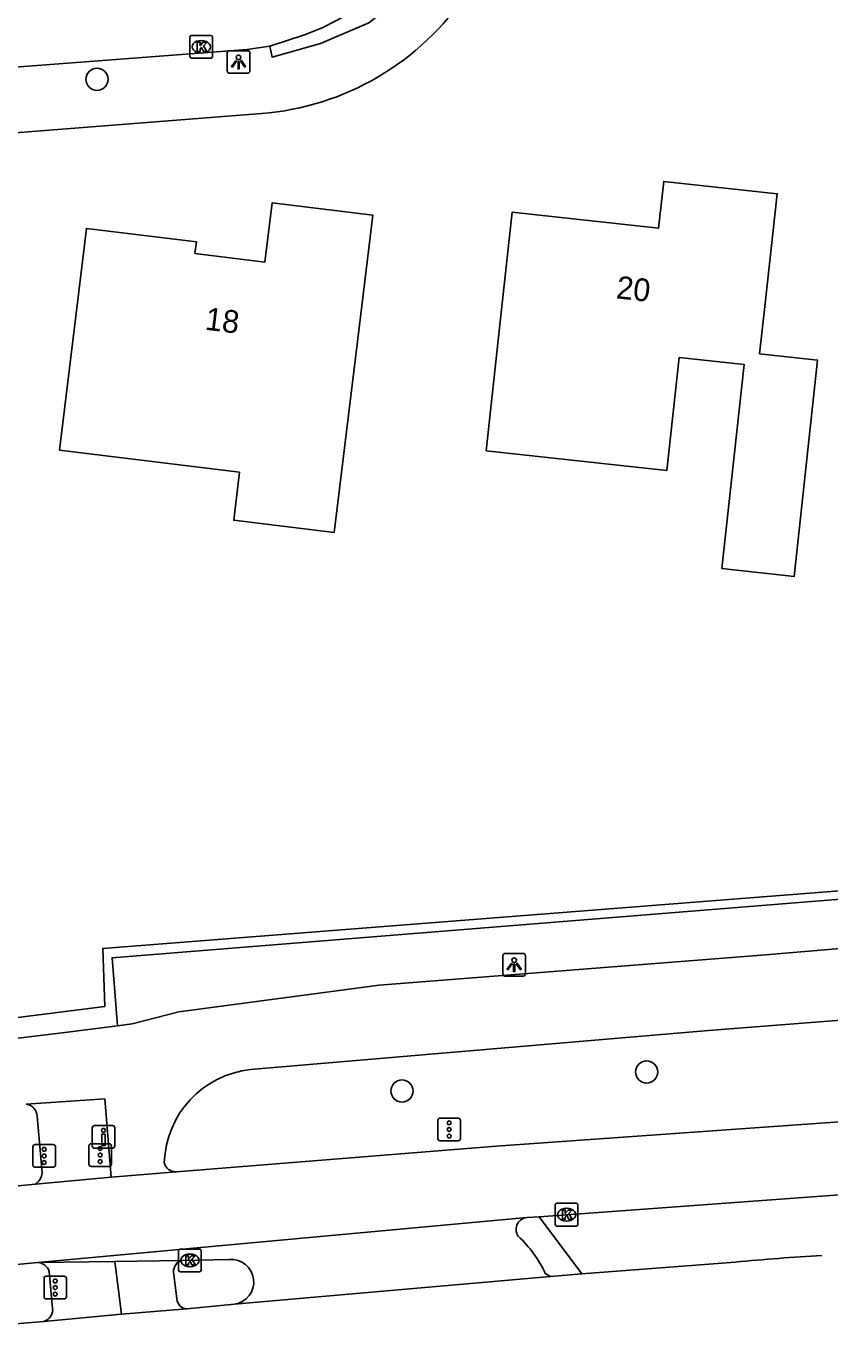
# Model space of a CAD drawing. Extents: x 162398 to 163643, y 386453 to 387397.
# Drawn here: x 163129.2 to 163164.7, y 386513.4 to 386571.3 of the extents above; entities that cross this region are included whole.
import ezdxf

# ---------------------------------------------------------------- set-up
doc = ezdxf.new("R2010")
doc.units = 0
for name, color, linetype in [('IMGEO_Boom', 7, 'Continuous'), ('IMGEO_Drukknoppaal', 7, 'Continuous'), ('IMGEO_Fietspad_gesloten', 7, 'Continuous'), ('IMGEO_Groenvoorziening', 7, 'Continuous'), ('IMGEO_Kolk', 7, 'Continuous'), ('IMGEO_Lichtpunt', 7, 'Continuous'), ('IMGEO_Muur', 7, 'Continuous'), ('IMGEO_Pand', 7, 'Continuous'), ('IMGEO_Pand_nummerreeks', 7, 'Continuous'), ('IMGEO_Rijbaan_lokaal_open', 7, 'Continuous'), ('IMGEO_Rijbaan_regionaal_gesloten', 7, 'Continuous'), ('IMGEO_Verkeerseiland_gesloten', 7, 'Continuous'), ('IMGEO_Verkeersregelinstallatiepaal', 7, 'Continuous'), ('IMGEO_Voetpad_open', 7, 'Continuous')]:
    doc.layers.add(name, color=color, linetype=linetype)

msp = doc.modelspace()

# ---------------------------------------------------------------- linework, layer by layer
at = {"layer": 'IMGEO_Boom'}
for centre in [(163132.363, 386568.962), (163156.594, 386525.203), (163145.81, 386524.365)]:
    msp.add_circle(centre, 0.489, dxfattribs=at)
at = {"layer": 'IMGEO_Drukknoppaal'}
for p, q in [((163132.158, 386521.941), (163132.158, 386522.741)), ((163132.158, 386522.741), (163132.158, 386521.941)), ((163132.258, 386522.841), (163133.048, 386522.841)), ((163133.048, 386522.841), (163132.258, 386522.841)), ((163133.148, 386522.741), (163133.148, 386521.941)), ((163133.148, 386521.941), (163133.148, 386522.741)), ((163133.048, 386521.841), (163132.258, 386521.841)), ((163132.258, 386521.841), (163133.048, 386521.841))]:
    msp.add_line(p, q, dxfattribs=at)
msp.add_lwpolyline([(163132.728, 386522.466), (163132.728, 386521.966), (163132.578, 386521.966), (163132.578, 386522.466), (163132.728, 386522.466)], dxfattribs=at)
msp.add_circle((163132.653, 386522.631), 0.085, dxfattribs=at)
for centre, start, end in [((163132.258, 386522.741), 90, 180), ((163132.258, 386522.741), 90, 180), ((163133.048, 386522.741), 0, 90), ((163133.048, 386522.741), 360, 90), ((163132.258, 386521.941), 180, 270), ((163132.258, 386521.941), 180, 270), ((163133.048, 386521.941), 270, 0), ((163133.048, 386521.941), 270, 0)]:
    msp.add_arc(centre, 0.1, start, end, dxfattribs=at)
at = {"layer": 'IMGEO_Fietspad_gesloten'}
for points in [[(163185.658, 386532.373), (163161.664, 386530.357), (163144.807, 386529.027), (163135.975, 386527.848), (163133.919, 386527.328), (163133.263, 386527.23)], [(163139.134, 386525.309), (163159.33, 386527.037), (163183.268, 386528.893)], [(163130.826, 386526.923), (163133.263, 386527.23)], [(163129.247, 386523.78), (163132.704, 386524.019), (163132.995, 386520.565)], [(163133.156, 386516.856), (163133.445, 386514.52)], [(163135.74, 386516.394), (163135.882, 386515.206)]]:
    msp.add_lwpolyline(points, dxfattribs=at)
for centre, radius, start, end in [((163086.566, 386887.267), 363.052, 274.54557, 277.00234), ((163139.584, 386521.078), 4.254, 96.07539, 178.17431), ((163135.832, 386521.311), 0.509, 190.95908, 274.28557), ((163136.224, 386516.42), 0.485, 104.47781, 183.12476), ((163136.355, 386515.23), 0.473, 182.85659, 267.14341)]:
    msp.add_arc(centre, radius, start, end, dxfattribs=at)
at = {"layer": 'IMGEO_Groenvoorziening'}
msp.add_lwpolyline([(163243.313, 386542.596), (163241.901, 386539.593), (163239.582, 386537.387), (163183.884, 386534.66), (163132.616, 386530.652), (163132.716, 386528.091), (163121.414, 386526.667), (163107.365, 386525.735)], dxfattribs=at)
at = {"layer": 'IMGEO_Kolk'}
for p, q in [((163136.462, 386569.968), (163136.462, 386570.82)), ((163136.537, 386570.894), (163137.389, 386570.894)), ((163136.95, 386570.674), (163136.975, 386570.674)), ((163137.463, 386570.82), (163137.463, 386569.968)), ((163136.973, 386570.114), (163136.948, 386570.114)), ((163137.389, 386569.894), (163136.537, 386569.894)), ((163152.567, 386518.487), (163152.567, 386519.339)), ((163152.642, 386519.413), (163153.494, 386519.413)), ((163153.055, 386519.193), (163153.08, 386519.193)), ((163153.568, 386519.339), (163153.568, 386518.487)), ((163153.494, 386518.413), (163152.642, 386518.413)), ((163153.078, 386518.633), (163153.053, 386518.633)), ((163135.959, 386516.472), (163135.959, 386517.324)), ((163136.034, 386517.398), (163136.886, 386517.398)), ((163136.96, 386517.324), (163136.96, 386516.472)), ((163136.447, 386517.178), (163136.472, 386517.178)), ((163136.886, 386516.398), (163136.034, 386516.398)), ((163136.47, 386516.618), (163136.445, 386516.618))]:
    msp.add_line(p, q, dxfattribs=at)
for points in [[(163136.462, 386569.968), (163136.462, 386570.82)], [(163136.537, 386570.894), (163137.389, 386570.894)], [(163136.783, 386570.594), (163136.906, 386570.594), (163136.906, 386570.443), (163137.036, 386570.594), (163137.2, 386570.594), (163137.054, 386570.443), (163137.207, 386570.194), (163137.055, 386570.194), (163136.97, 386570.358), (163136.906, 386570.291), (163136.906, 386570.194), (163136.783, 386570.194), (163136.783, 386570.594)], [(163137.463, 386570.82), (163137.463, 386569.968)], [(163137.389, 386569.894), (163136.537, 386569.894)], [(163152.567, 386518.487), (163152.567, 386519.339)], [(163152.642, 386519.413), (163153.494, 386519.413)], [(163152.888, 386519.113), (163153.011, 386519.113), (163153.011, 386518.962), (163153.141, 386519.113), (163153.305, 386519.113), (163153.159, 386518.962), (163153.312, 386518.713), (163153.16, 386518.713), (163153.075, 386518.877), (163153.011, 386518.81), (163153.011, 386518.713), (163152.888, 386518.713), (163152.888, 386519.113)], [(163153.568, 386519.339), (163153.568, 386518.487)], [(163153.494, 386518.413), (163152.642, 386518.413)], [(163135.959, 386516.472), (163135.959, 386517.324)], [(163136.034, 386517.398), (163136.886, 386517.398)], [(163136.96, 386517.324), (163136.96, 386516.472)], [(163136.28, 386517.098), (163136.403, 386517.098), (163136.403, 386516.947), (163136.533, 386517.098), (163136.697, 386517.098), (163136.551, 386516.947), (163136.704, 386516.698), (163136.552, 386516.698), (163136.467, 386516.862), (163136.403, 386516.795), (163136.403, 386516.698), (163136.28, 386516.698), (163136.28, 386517.098)], [(163136.886, 386516.398), (163136.034, 386516.398)]]:
    msp.add_lwpolyline(points, dxfattribs=at)
for centre, start, end in [((163136.539, 386570.818), 91.55205, 178.44795), ((163136.539, 386570.818), 91.55205, 178.44795), ((163137.387, 386570.818), 1.55205, 88.44795), ((163137.387, 386570.818), 1.55205, 88.44795), ((163136.539, 386569.97), 181.55205, 268.44795), ((163136.539, 386569.97), 181.55205, 268.44795), ((163137.387, 386569.97), 271.55205, 358.44795), ((163137.387, 386569.97), 271.55205, 358.44795), ((163152.644, 386519.337), 91.55205, 178.44795), ((163152.644, 386519.337), 91.55205, 178.44795), ((163153.492, 386519.337), 1.55205, 88.44795), ((163153.492, 386519.337), 1.55205, 88.44795), ((163152.644, 386518.489), 181.55205, 268.44795), ((163152.644, 386518.489), 181.55205, 268.44795), ((163153.492, 386518.489), 271.55205, 358.44795), ((163153.492, 386518.489), 271.55205, 358.44795), ((163136.036, 386517.322), 91.55205, 178.44795), ((163136.036, 386517.322), 91.55205, 178.44795), ((163136.884, 386517.322), 1.55205, 88.44795), ((163136.884, 386517.322), 1.55205, 88.44795), ((163136.036, 386516.474), 181.55205, 268.44795), ((163136.036, 386516.474), 181.55205, 268.44795), ((163136.884, 386516.474), 271.55205, 358.44795), ((163136.884, 386516.474), 271.55205, 358.44795)]:
    msp.add_arc(centre, 0.0765, start, end, dxfattribs=at)
for centre, major_axis, ratio, start_param, end_param in [((163136.949, 386570.394), (-0.387, 0.002), 0.722429, 4.712389, 7.853982), ((163136.974, 386570.394), (-0.39, 0.002), 0.717154, 1.570796, 4.712389), ((163153.054, 386518.913), (-0.387, 0.002), 0.722429, 4.712389, 7.853982), ((163153.079, 386518.913), (-0.39, 0.002), 0.717154, 1.570796, 4.712389), ((163136.446, 386516.898), (-0.387, 0.002), 0.722429, 4.712389, 7.853982), ((163136.471, 386516.898), (-0.39, 0.002), 0.717154, 1.570796, 4.712389)]:
    msp.add_ellipse(centre, major_axis=major_axis, ratio=ratio, start_param=start_param, end_param=end_param, dxfattribs=at)
at = {"layer": 'IMGEO_Lichtpunt'}
for p, q in [((163138.106, 386570.129), (163138.106, 386569.322)), ((163138.106, 386570.129), (163138.106, 386569.322)), ((163139.008, 386570.224), (163138.2, 386570.224)), ((163139.008, 386570.224), (163138.2, 386570.224)), ((163139.102, 386569.322), (163139.102, 386570.129)), ((163139.102, 386569.322), (163139.102, 386570.129)), ((163138.2, 386569.228), (163139.008, 386569.228)), ((163138.2, 386569.228), (163139.008, 386569.228)), ((163150.257, 386530.333), (163150.257, 386529.526)), ((163150.257, 386530.333), (163150.257, 386529.526)), ((163151.159, 386530.428), (163150.351, 386530.428)), ((163151.159, 386530.428), (163150.351, 386530.428)), ((163151.253, 386529.526), (163151.253, 386530.333)), ((163151.253, 386529.526), (163151.253, 386530.333)), ((163150.351, 386529.432), (163151.159, 386529.432)), ((163150.351, 386529.432), (163151.159, 386529.432))]:
    msp.add_line(p, q, dxfattribs=at)
for points in [[(163138.48, 386569.793), (163138.519, 386569.765), (163138.331, 386569.503), (163138.293, 386569.53), (163138.48, 386569.793)], [(163138.582, 386569.745), (163138.629, 386569.745), (163138.629, 386569.423), (163138.582, 386569.423), (163138.582, 386569.745)], [(163138.692, 386569.765), (163138.73, 386569.792), (163138.917, 386569.53), (163138.878, 386569.502), (163138.692, 386569.765)], [(163150.631, 386529.997), (163150.67, 386529.969), (163150.482, 386529.707), (163150.444, 386529.734), (163150.631, 386529.997)], [(163150.733, 386529.949), (163150.78, 386529.949), (163150.78, 386529.627), (163150.733, 386529.627), (163150.733, 386529.949)], [(163150.843, 386529.969), (163150.881, 386529.996), (163151.068, 386529.734), (163151.029, 386529.706), (163150.843, 386529.969)]]:
    msp.add_lwpolyline(points, dxfattribs=at)
for centre in [(163138.605, 386569.927), (163150.756, 386530.131)]:
    msp.add_circle(centre, 0.0994, dxfattribs=at)
for centre, start, end in [((163138.2, 386570.129), 90, 180), ((163138.2, 386570.129), 90, 180), ((163139.008, 386570.129), 0, 90), ((163139.008, 386570.129), 0, 90), ((163138.2, 386569.322), 180, 270), ((163138.2, 386569.322), 180, 270), ((163139.008, 386569.322), 270, 0), ((163139.008, 386569.322), 270, 360), ((163150.351, 386530.333), 90, 180), ((163150.351, 386530.333), 90, 180), ((163151.159, 386530.333), 0, 90), ((163151.159, 386530.333), 0, 90), ((163150.351, 386529.526), 180, 270), ((163150.351, 386529.526), 180, 270), ((163151.159, 386529.526), 270, 0), ((163151.159, 386529.526), 270, 360)]:
    msp.add_arc(centre, 0.0946, start, end, dxfattribs=at)
at = {"layer": 'IMGEO_Muur'}
msp.add_lwpolyline([(163243.313, 386542.596), (163241.901, 386539.593), (163239.582, 386537.387), (163183.884, 386534.66), (163132.616, 386530.652), (163132.716, 386528.091), (163121.414, 386526.667), (163107.365, 386525.735)], dxfattribs=at)
at = {"layer": 'IMGEO_Pand'}
for points in [[(163149.516, 386552.585), (163150.126, 386558.138), (163150.671, 386563.108), (163157.121, 386562.4), (163157.348, 386564.464), (163162.352, 386563.915), (163161.806, 386558.945), (163161.578, 386556.866), (163164.13, 386556.586), (163163.104, 386547.044), (163159.913, 386547.394), (163160.901, 386556.385), (163158.033, 386556.7), (163157.486, 386551.71), (163149.516, 386552.585)], [(163138.652, 386551.65), (163130.705, 386552.62), (163131.292, 386557.427), (163131.898, 386562.39), (163136.744, 386561.799), (163136.681, 386561.283), (163139.761, 386560.907), (163140.08, 386563.514), (163144.523, 386562.971), (163143.917, 386558.008), (163142.816, 386548.985), (163138.393, 386549.525), (163138.652, 386551.65)]]:
    msp.add_lwpolyline(points, dxfattribs=at)
at = {"layer": 'IMGEO_Rijbaan_lokaal_open'}
for points in [[(163139.978, 386570.426), (163141.507, 386570.918), (163142.286, 386571.231), (163142.946, 386571.563), (163143.618, 386571.936), (163144.218, 386572.324), (163144.729, 386572.764)], [(163124.883, 386569.21), (163138.986, 386570.276), (163139.978, 386570.426)]]:
    msp.add_lwpolyline(points, dxfattribs=at)
at = {"layer": 'IMGEO_Rijbaan_regionaal_gesloten'}
for points in [[(163181, 386524.045), (163176.912, 386523.837), (163149.964, 386521.933), (163135.87, 386520.803)], [(163135.87, 386520.803), (163132.995, 386520.565)], [(163151.86, 386518.825), (163165.514, 386519.821), (163181.166, 386520.849)], [(163129.649, 386520.259), (163107.763, 386518.15)], [(163132.995, 386520.565), (163129.649, 386520.259)], [(163129.754, 386516.804), (163151.308, 386518.789)], [(163151.308, 386518.789), (163151.86, 386518.825)], [(163113.263, 386515.243), (163129.754, 386516.804)], [(163129.754, 386516.804), (163133.156, 386516.856)], [(163133.156, 386516.856), (163136.103, 386516.89)], [(163136.103, 386516.89), (163138.197, 386516.937)], [(163160.5, 386516.821), (163153.745, 386516.299)], [(163152.351, 386516.19), (163138.426, 386514.97)], [(163152.351, 386516.19), (163152.129, 386516.322)], [(163153.745, 386516.299), (163152.351, 386516.19)], [(163138.426, 386514.97), (163136.331, 386514.757)], [(163133.445, 386514.52), (163130.019, 386514.208)], [(163136.331, 386514.757), (163133.445, 386514.52)], [(163130.019, 386514.208), (163119.609, 386513.357)]]:
    msp.add_lwpolyline(points, dxfattribs=at)
for centre, radius, start, end in [((163151.375, 386518.261), 0.535, 150.47558, 214.19489), ((163151.373, 386518.261), 0.532, 96.96446, 150.34921), ((163147.393, 386514.12), 5.222, 24.93869, 47.33206), ((163138.285, 386515.95), 0.99, 278.17523, 95.10584), ((163170.474, 386412.744), 104.554, 93.37433, 95.47429)]:
    msp.add_arc(centre, radius, start, end, dxfattribs=at)
at = {"layer": 'IMGEO_Verkeerseiland_gesloten'}
msp.add_lwpolyline([(163151.86, 386518.825), (163153.745, 386516.299)], dxfattribs=at)
at = {"layer": 'IMGEO_Verkeersregelinstallatiepaal'}
for p, q in [((163147.395, 386522.269), (163147.395, 386523.069)), ((163147.395, 386523.069), (163147.395, 386522.269)), ((163147.495, 386523.169), (163148.285, 386523.169)), ((163148.285, 386523.169), (163147.495, 386523.169)), ((163148.385, 386523.069), (163148.385, 386522.269)), ((163148.385, 386522.269), (163148.385, 386523.069)), ((163129.541, 386521.102), (163129.541, 386521.902)), ((163129.541, 386521.902), (163129.541, 386521.102)), ((163129.641, 386522.002), (163130.431, 386522.002)), ((163130.431, 386522.002), (163129.641, 386522.002)), ((163130.531, 386521.902), (163130.531, 386521.102)), ((163130.531, 386521.102), (163130.531, 386521.902)), ((163132.009, 386521.142), (163132.009, 386521.942)), ((163132.009, 386521.942), (163132.009, 386521.142)), ((163132.109, 386522.042), (163132.899, 386522.042)), ((163132.899, 386522.042), (163132.109, 386522.042)), ((163132.999, 386521.942), (163132.999, 386521.142)), ((163132.999, 386521.142), (163132.999, 386521.942)), ((163148.285, 386522.169), (163147.495, 386522.169)), ((163147.495, 386522.169), (163148.285, 386522.169)), ((163130.431, 386521.002), (163129.641, 386521.002)), ((163129.641, 386521.002), (163130.431, 386521.002)), ((163132.899, 386521.042), (163132.109, 386521.042)), ((163132.109, 386521.042), (163132.899, 386521.042)), ((163130.028, 386515.3), (163130.028, 386516.1)), ((163130.028, 386516.1), (163130.028, 386515.3)), ((163130.128, 386516.2), (163130.918, 386516.2)), ((163130.918, 386516.2), (163130.128, 386516.2)), ((163131.018, 386516.1), (163131.018, 386515.3)), ((163131.018, 386515.3), (163131.018, 386516.1)), ((163130.918, 386515.2), (163130.128, 386515.2)), ((163130.128, 386515.2), (163130.918, 386515.2))]:
    msp.add_line(p, q, dxfattribs=at)
for centre in [(163147.89, 386522.959), (163147.89, 386522.669), (163147.89, 386522.379), (163130.036, 386521.792), (163132.504, 386521.832), (163130.036, 386521.502), (163130.036, 386521.212), (163132.504, 386521.542), (163132.504, 386521.252), (163130.523, 386515.99), (163130.523, 386515.7), (163130.523, 386515.41)]:
    msp.add_circle(centre, 0.085, dxfattribs=at)
for centre, start, end in [((163147.495, 386523.069), 90, 180), ((163147.495, 386523.069), 90, 180), ((163148.285, 386523.069), 0, 90), ((163148.285, 386523.069), 360, 90), ((163129.641, 386521.902), 90, 180), ((163129.641, 386521.902), 90, 180), ((163130.431, 386521.902), 0, 90), ((163130.431, 386521.902), 360, 90), ((163132.109, 386521.942), 90, 180), ((163132.109, 386521.942), 90, 180), ((163132.899, 386521.942), 0, 90), ((163132.899, 386521.942), 360, 90), ((163147.495, 386522.269), 180, 270), ((163147.495, 386522.269), 180, 270), ((163148.285, 386522.269), 270, 0), ((163148.285, 386522.269), 270, 0), ((163129.641, 386521.102), 180, 270), ((163129.641, 386521.102), 180, 270), ((163130.431, 386521.102), 270, 0), ((163130.431, 386521.102), 270, 0), ((163132.109, 386521.142), 180, 270), ((163132.109, 386521.142), 180, 270), ((163132.899, 386521.142), 270, 0), ((163132.899, 386521.142), 270, 0), ((163130.128, 386516.1), 90, 180), ((163130.128, 386516.1), 90, 180), ((163130.918, 386516.1), 0, 90), ((163130.918, 386516.1), 360, 90), ((163130.128, 386515.3), 180, 270), ((163130.128, 386515.3), 180, 270), ((163130.918, 386515.3), 270, 0), ((163130.918, 386515.3), 270, 0)]:
    msp.add_arc(centre, 0.1, start, end, dxfattribs=at)
at = {"layer": 'IMGEO_Voetpad_open'}
for points in [[(163144.729, 386572.764), (163145.121, 386572.056), (163144.342, 386571.445), (163142.219, 386570.544), (163140.082, 386569.938), (163139.978, 386570.426)], [(163139.616, 386567.455), (163000, 386556.492), (162997.872, 386556.325)], [(163133.263, 386527.23), (163133.027, 386530.235), (163183.936, 386534.334), (163217.254, 386535.858), (163239.82, 386537.047), (163242.352, 386539.4), (163243.688, 386542.308)], [(163129.951, 386520.763), (163129.727, 386523.251)], [(163130.409, 386514.78), (163130.251, 386516.414)]]:
    msp.add_lwpolyline(points, dxfattribs=at)
for centre, radius, start, end in [((163138.688, 386579.413), 11.994, 274.43625, 326.32265), ((163129.182, 386523.239), 0.545, 1.24125, 83.19821), ((163129.229, 386520.853), 0.728, 305.26881, 352.87057), ((163129.732, 386516.265), 0.54, 16.0416, 87.71526), ((163129.878, 386514.723), 0.534, 285.32619, 6.10006)]:
    msp.add_arc(centre, radius, start, end, dxfattribs=at)

# ---------------------------------------------------------------- texts
at = {"layer": 'IMGEO_Pand_nummerreeks'}
for s, rotation, p in [('20', 353.73587, (163155.222, 386559.309)), ('18', 353.03989, (163137.097, 386557.928))]:
    msp.add_text(s, height=1, rotation=rotation, dxfattribs=at).set_placement(p)

doc.saveas('drawing.dxf')
